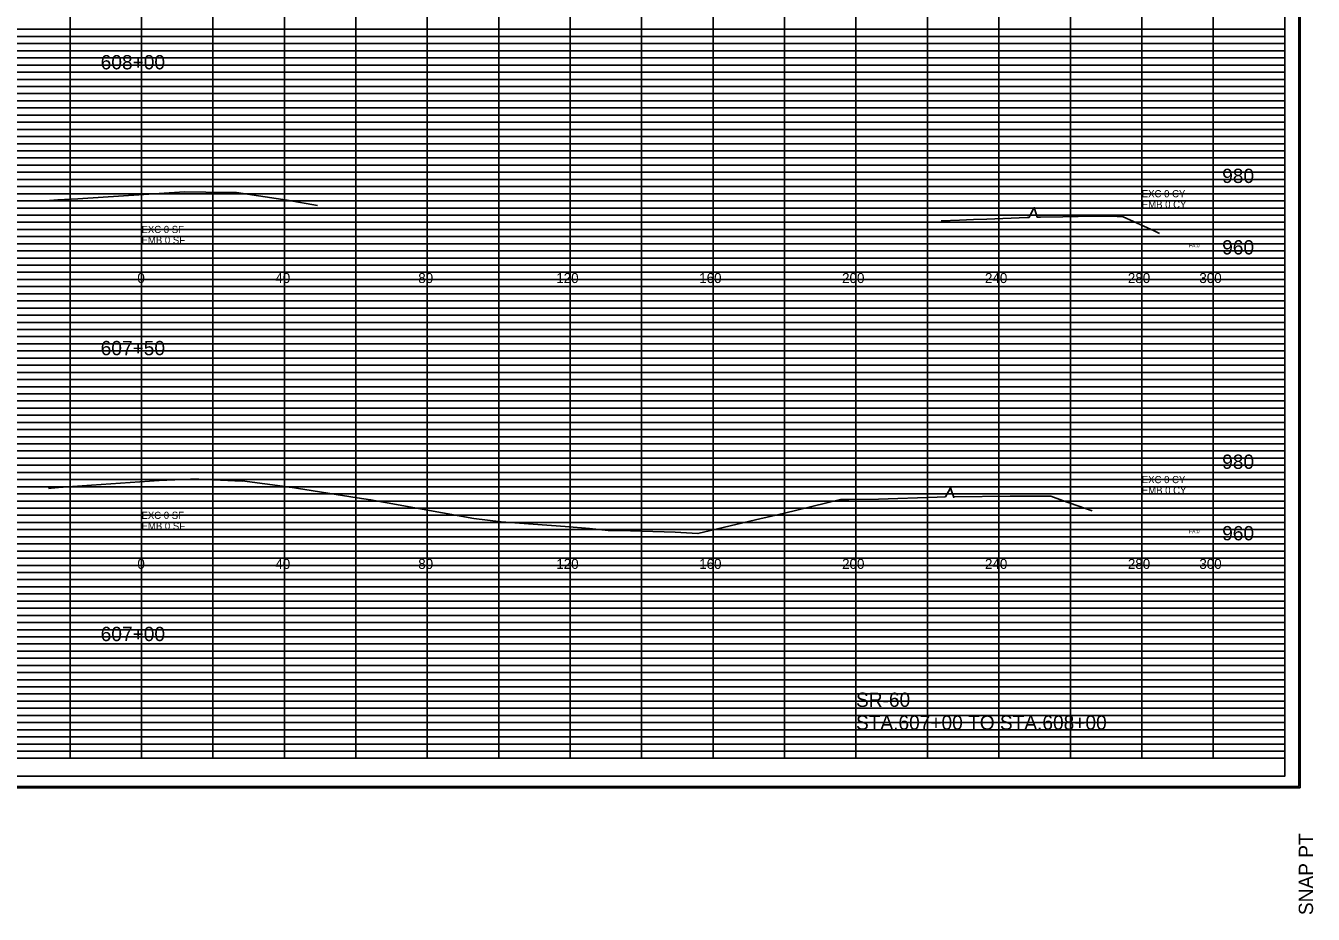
# Model space of a CAD drawing. Extents: x 2313580 to 2322968, y 282099 to 303247.
# Drawn here: x 2321124.9 to 2321485.3, y 287544 to 287792.7 of the extents above; entities that cross this region are included whole.
import ezdxf

# ---------------------------------------------------------------- set-up
doc = ezdxf.new("R2010")
doc.units = 0
for name, color, linetype in [('DESIGN - EARTHWORK - Excavation Limit Lines', 7, 'Continuous'), ('DESIGN - SHEET - Corner Text', 7, 'Continuous'), ('DESIGN - SHEET - Light Grid', 7, 'Continuous'), ('DESIGN - SHEET - Linework', 7, 'Continuous'), ('DESIGN - SHEET - Plot Shape', 7, 'Continuous'), ('DESIGN - TYPICAL - Text', 7, 'Continuous'), ('Prop_ CL text', 7, 'Continuous'), ('SURVEY - GROUND - Top of Ground', 7, 'Continuous')]:
    doc.layers.add(name, color=color, linetype=linetype)

msp = doc.modelspace()

# ---------------------------------------------------------------- linework, layer by layer
at = {"layer": 'DESIGN - SHEET - Light Grid'}
for p, q in [((2320997.28, 287791.67), (2321157.28, 287791.67)), ((2320997.28, 287789.67), (2321157.28, 287789.67)), ((2321157.28, 287791.67), (2321317.28, 287791.67)), ((2321157.28, 287789.67), (2321317.28, 287789.67)), ((2321317.28, 287791.67), (2321477.28, 287791.67)), ((2321317.28, 287789.67), (2321477.28, 287789.67)), ((2320997.28, 287785.67), (2321157.28, 287785.67)), ((2320997.28, 287783.67), (2321157.28, 287783.67)), ((2321157.28, 287785.67), (2321317.28, 287785.67)), ((2321157.28, 287783.67), (2321317.28, 287783.67)), ((2321317.28, 287785.67), (2321477.28, 287785.67)), ((2321317.28, 287783.67), (2321477.28, 287783.67)), ((2320997.28, 287781.67), (2321157.28, 287781.67)), ((2320997.28, 287779.67), (2321157.28, 287779.67)), ((2321157.28, 287781.67), (2321317.28, 287781.67)), ((2321157.28, 287779.67), (2321317.28, 287779.67)), ((2321317.28, 287781.67), (2321477.28, 287781.67)), ((2321317.28, 287779.67), (2321477.28, 287779.67)), ((2320997.28, 287777.67), (2321157.28, 287777.67)), ((2320997.28, 287775.67), (2321157.28, 287775.67)), ((2321157.28, 287777.67), (2321317.28, 287777.67)), ((2321157.28, 287775.67), (2321317.28, 287775.67)), ((2321317.28, 287777.67), (2321477.28, 287777.67)), ((2321317.28, 287775.67), (2321477.28, 287775.67)), ((2320997.28, 287773.67), (2321157.28, 287773.67)), ((2320997.28, 287771.67), (2321157.28, 287771.67)), ((2321157.28, 287773.67), (2321317.28, 287773.67)), ((2321157.28, 287771.67), (2321317.28, 287771.67)), ((2321317.28, 287773.67), (2321477.28, 287773.67)), ((2321317.28, 287771.67), (2321477.28, 287771.67)), ((2320997.28, 287769.67), (2321157.28, 287769.67)), ((2321157.28, 287769.67), (2321317.28, 287769.67)), ((2321317.28, 287769.67), (2321477.28, 287769.67)), ((2320997.28, 287765.67), (2321157.28, 287765.67)), ((2321157.28, 287765.67), (2321317.28, 287765.67)), ((2321317.28, 287765.67), (2321477.28, 287765.67)), ((2320997.28, 287763.67), (2321157.28, 287763.67)), ((2320997.28, 287761.67), (2321157.28, 287761.67)), ((2321157.28, 287763.67), (2321317.28, 287763.67)), ((2321157.28, 287761.67), (2321317.28, 287761.67)), ((2321317.28, 287763.67), (2321477.28, 287763.67)), ((2321317.28, 287761.67), (2321477.28, 287761.67)), ((2320997.28, 287759.67), (2321157.28, 287759.67)), ((2320997.28, 287757.67), (2321157.28, 287757.67)), ((2321157.28, 287759.67), (2321317.28, 287759.67)), ((2321157.28, 287757.67), (2321317.28, 287757.67)), ((2321317.28, 287759.67), (2321477.28, 287759.67)), ((2321317.28, 287757.67), (2321477.28, 287757.67)), ((2320997.28, 287755.67), (2321157.28, 287755.67)), ((2320997.28, 287753.67), (2321157.28, 287753.67)), ((2321157.28, 287755.67), (2321317.28, 287755.67)), ((2321157.28, 287753.67), (2321317.28, 287753.67)), ((2321317.28, 287755.67), (2321477.28, 287755.67)), ((2321317.28, 287753.67), (2321477.28, 287753.67)), ((2320997.28, 287751.67), (2321157.28, 287751.67)), ((2321157.28, 287751.67), (2321317.28, 287751.67)), ((2321317.28, 287751.67), (2321477.28, 287751.67)), ((2320997.28, 287749.67), (2321157.28, 287749.67)), ((2321157.28, 287749.67), (2321317.28, 287749.67)), ((2321317.28, 287749.67), (2321477.28, 287749.67)), ((2320997.28, 287745.67), (2321157.28, 287745.67)), ((2320997.28, 287743.67), (2321157.28, 287743.67)), ((2321157.28, 287745.67), (2321317.28, 287745.67)), ((2321157.28, 287743.67), (2321317.28, 287743.67)), ((2321317.28, 287745.67), (2321477.28, 287745.67)), ((2321317.28, 287743.67), (2321477.28, 287743.67)), ((2320997.28, 287741.67), (2321157.28, 287741.67)), ((2320997.28, 287739.67), (2321157.28, 287739.67)), ((2321157.28, 287741.67), (2321317.28, 287741.67)), ((2321157.28, 287739.67), (2321317.28, 287739.67)), ((2321317.28, 287741.67), (2321477.28, 287741.67)), ((2321317.28, 287739.67), (2321477.28, 287739.67)), ((2320997.28, 287737.67), (2321157.28, 287737.67)), ((2320997.28, 287735.67), (2321157.28, 287735.67)), ((2321157.28, 287737.67), (2321317.28, 287737.67)), ((2321157.28, 287735.67), (2321317.28, 287735.67)), ((2321317.28, 287737.67), (2321477.28, 287737.67)), ((2321317.28, 287735.67), (2321477.28, 287735.67)), ((2320997.28, 287733.67), (2321157.28, 287733.67)), ((2321157.28, 287733.67), (2321317.28, 287733.67)), ((2321317.28, 287733.67), (2321477.28, 287733.67)), ((2320997.28, 287731.67), (2321157.28, 287731.67)), ((2320997.28, 287729.67), (2321157.28, 287729.67)), ((2321157.28, 287731.67), (2321317.28, 287731.67)), ((2321157.28, 287729.67), (2321317.28, 287729.67)), ((2321317.28, 287731.67), (2321477.28, 287731.67)), ((2321317.28, 287729.67), (2321477.28, 287729.67)), ((2320997.28, 287725.67), (2321157.28, 287725.67)), ((2321157.28, 287725.67), (2321317.28, 287725.67)), ((2321317.28, 287725.67), (2321477.28, 287725.67)), ((2320997.28, 287723.67), (2321157.28, 287723.67)), ((2320997.28, 287721.67), (2321157.28, 287721.67)), ((2321157.28, 287723.67), (2321317.28, 287723.67)), ((2321157.28, 287721.67), (2321317.28, 287721.67)), ((2321317.28, 287723.67), (2321477.28, 287723.67)), ((2321317.28, 287721.67), (2321477.28, 287721.67)), ((2320997.28, 287719.67), (2321157.28, 287719.67)), ((2320997.28, 287717.67), (2321157.28, 287717.67)), ((2321157.28, 287719.67), (2321317.28, 287719.67)), ((2321157.28, 287717.67), (2321317.28, 287717.67)), ((2321317.28, 287719.67), (2321477.28, 287719.67)), ((2321317.28, 287717.67), (2321477.28, 287717.67)), ((2320997.28, 287715.67), (2321157.28, 287715.67)), ((2321157.28, 287715.67), (2321317.28, 287715.67)), ((2321317.28, 287715.67), (2321477.28, 287715.67)), ((2320997.28, 287713.67), (2321157.28, 287713.67)), ((2320997.28, 287711.67), (2321157.28, 287711.67)), ((2321157.28, 287713.67), (2321317.28, 287713.67)), ((2321157.28, 287711.67), (2321317.28, 287711.67)), ((2321317.28, 287713.67), (2321477.28, 287713.67)), ((2321317.28, 287711.67), (2321477.28, 287711.67)), ((2320997.28, 287709.67), (2321157.28, 287709.67)), ((2321157.28, 287709.67), (2321317.28, 287709.67)), ((2321317.28, 287709.67), (2321477.28, 287709.67)), ((2320997.28, 287705.67), (2321157.28, 287705.67)), ((2320997.28, 287703.67), (2321157.28, 287703.67)), ((2321157.28, 287705.67), (2321317.28, 287705.67)), ((2321157.28, 287703.67), (2321317.28, 287703.67)), ((2321317.28, 287705.67), (2321477.28, 287705.67)), ((2321317.28, 287703.67), (2321477.28, 287703.67)), ((2320997.28, 287701.67), (2321157.28, 287701.67)), ((2320997.28, 287699.67), (2321157.28, 287699.67)), ((2321157.28, 287701.67), (2321317.28, 287701.67)), ((2321157.28, 287699.67), (2321317.28, 287699.67)), ((2321317.28, 287701.67), (2321477.28, 287701.67)), ((2321317.28, 287699.67), (2321477.28, 287699.67)), ((2320997.28, 287697.67), (2321157.28, 287697.67)), ((2321157.28, 287697.67), (2321317.28, 287697.67)), ((2321317.28, 287697.67), (2321477.28, 287697.67)), ((2320997.28, 287695.67), (2321157.28, 287695.67)), ((2320997.28, 287693.67), (2321157.28, 287693.67)), ((2321157.28, 287695.67), (2321317.28, 287695.67)), ((2321157.28, 287693.67), (2321317.28, 287693.67)), ((2321317.28, 287695.67), (2321477.28, 287695.67)), ((2321317.28, 287693.67), (2321477.28, 287693.67)), ((2320997.28, 287691.67), (2321157.28, 287691.67)), ((2320997.28, 287689.67), (2321157.28, 287689.67)), ((2321157.28, 287691.67), (2321317.28, 287691.67)), ((2321157.28, 287689.67), (2321317.28, 287689.67)), ((2321317.28, 287691.67), (2321477.28, 287691.67)), ((2321317.28, 287689.67), (2321477.28, 287689.67)), ((2320997.28, 287685.67), (2321157.28, 287685.67)), ((2321157.28, 287685.67), (2321317.28, 287685.67)), ((2321317.28, 287685.67), (2321477.28, 287685.67)), ((2320997.28, 287683.67), (2321157.28, 287683.67)), ((2320997.28, 287681.67), (2321157.28, 287681.67)), ((2321157.28, 287683.67), (2321317.28, 287683.67)), ((2321157.28, 287681.67), (2321317.28, 287681.67)), ((2321317.28, 287683.67), (2321477.28, 287683.67)), ((2321317.28, 287681.67), (2321477.28, 287681.67)), ((2320997.28, 287679.67), (2321157.28, 287679.67)), ((2321157.28, 287679.67), (2321317.28, 287679.67)), ((2321317.28, 287679.67), (2321477.28, 287679.67)), ((2320997.28, 287677.67), (2321157.28, 287677.67)), ((2320997.28, 287675.67), (2321157.28, 287675.67)), ((2321157.28, 287677.67), (2321317.28, 287677.67)), ((2321157.28, 287675.67), (2321317.28, 287675.67)), ((2321317.28, 287677.67), (2321477.28, 287677.67)), ((2321317.28, 287675.67), (2321477.28, 287675.67)), ((2320997.28, 287673.67), (2321157.28, 287673.67)), ((2320997.28, 287671.67), (2321157.28, 287671.67)), ((2321157.28, 287673.67), (2321317.28, 287673.67)), ((2321157.28, 287671.67), (2321317.28, 287671.67)), ((2321317.28, 287673.67), (2321477.28, 287673.67)), ((2321317.28, 287671.67), (2321477.28, 287671.67)), ((2320997.28, 287669.67), (2321157.28, 287669.67)), ((2321157.28, 287669.67), (2321317.28, 287669.67)), ((2321317.28, 287669.67), (2321477.28, 287669.67)), ((2320997.28, 287665.67), (2321157.28, 287665.67)), ((2320997.28, 287663.67), (2321157.28, 287663.67)), ((2321157.28, 287665.67), (2321317.28, 287665.67)), ((2321157.28, 287663.67), (2321317.28, 287663.67)), ((2321317.28, 287665.67), (2321477.28, 287665.67)), ((2321317.28, 287663.67), (2321477.28, 287663.67)), ((2320997.28, 287661.67), (2321157.28, 287661.67)), ((2321157.28, 287661.67), (2321317.28, 287661.67)), ((2321317.28, 287661.67), (2321477.28, 287661.67)), ((2320997.28, 287659.67), (2321157.28, 287659.67)), ((2320997.28, 287657.67), (2321157.28, 287657.67)), ((2321157.28, 287659.67), (2321317.28, 287659.67)), ((2321157.28, 287657.67), (2321317.28, 287657.67)), ((2321317.28, 287659.67), (2321477.28, 287659.67)), ((2321317.28, 287657.67), (2321477.28, 287657.67)), ((2320997.28, 287655.67), (2321157.28, 287655.67)), ((2320997.28, 287653.67), (2321157.28, 287653.67)), ((2321157.28, 287655.67), (2321317.28, 287655.67)), ((2321157.28, 287653.67), (2321317.28, 287653.67)), ((2321317.28, 287655.67), (2321477.28, 287655.67)), ((2321317.28, 287653.67), (2321477.28, 287653.67)), ((2320997.28, 287651.67), (2321157.28, 287651.67)), ((2320997.28, 287649.67), (2321157.28, 287649.67)), ((2321157.28, 287651.67), (2321317.28, 287651.67)), ((2321157.28, 287649.67), (2321317.28, 287649.67)), ((2321317.28, 287651.67), (2321477.28, 287651.67)), ((2321317.28, 287649.67), (2321477.28, 287649.67)), ((2320997.28, 287645.67), (2321157.28, 287645.67)), ((2321157.28, 287645.67), (2321317.28, 287645.67)), ((2321317.28, 287645.67), (2321477.28, 287645.67)), ((2320997.28, 287643.67), (2321157.28, 287643.67)), ((2321157.28, 287643.67), (2321317.28, 287643.67)), ((2321317.28, 287643.67), (2321477.28, 287643.67)), ((2320997.28, 287641.67), (2321157.28, 287641.67)), ((2320997.28, 287639.67), (2321157.28, 287639.67)), ((2321157.28, 287641.67), (2321317.28, 287641.67)), ((2321157.28, 287639.67), (2321317.28, 287639.67)), ((2321317.28, 287641.67), (2321477.28, 287641.67)), ((2321317.28, 287639.67), (2321477.28, 287639.67)), ((2320997.28, 287637.67), (2321157.28, 287637.67)), ((2320997.28, 287635.67), (2321157.28, 287635.67)), ((2321157.28, 287637.67), (2321317.28, 287637.67)), ((2321157.28, 287635.67), (2321317.28, 287635.67)), ((2321317.28, 287637.67), (2321477.28, 287637.67)), ((2321317.28, 287635.67), (2321477.28, 287635.67)), ((2320997.28, 287633.67), (2321157.28, 287633.67)), ((2320997.28, 287631.67), (2321157.28, 287631.67)), ((2321157.28, 287633.67), (2321317.28, 287633.67)), ((2321157.28, 287631.67), (2321317.28, 287631.67)), ((2321317.28, 287633.67), (2321477.28, 287633.67)), ((2321317.28, 287631.67), (2321477.28, 287631.67)), ((2320997.28, 287629.67), (2321157.28, 287629.67)), ((2321157.28, 287629.67), (2321317.28, 287629.67)), ((2321317.28, 287629.67), (2321477.28, 287629.67)), ((2320997.28, 287625.67), (2321157.28, 287625.67)), ((2321157.28, 287625.67), (2321317.28, 287625.67)), ((2321317.28, 287625.67), (2321477.28, 287625.67)), ((2320997.28, 287623.67), (2321157.28, 287623.67)), ((2320997.28, 287621.67), (2321157.28, 287621.67)), ((2321157.28, 287623.67), (2321317.28, 287623.67)), ((2321157.28, 287621.67), (2321317.28, 287621.67)), ((2321317.28, 287623.67), (2321477.28, 287623.67)), ((2321317.28, 287621.67), (2321477.28, 287621.67)), ((2320997.28, 287619.67), (2321157.28, 287619.67)), ((2320997.28, 287617.67), (2321157.28, 287617.67)), ((2321157.28, 287619.67), (2321317.28, 287619.67)), ((2321157.28, 287617.67), (2321317.28, 287617.67)), ((2321317.28, 287619.67), (2321477.28, 287619.67)), ((2321317.28, 287617.67), (2321477.28, 287617.67)), ((2320997.28, 287615.67), (2321157.28, 287615.67)), ((2320997.28, 287613.67), (2321157.28, 287613.67)), ((2321157.28, 287615.67), (2321317.28, 287615.67)), ((2321157.28, 287613.67), (2321317.28, 287613.67)), ((2321317.28, 287615.67), (2321477.28, 287615.67)), ((2321317.28, 287613.67), (2321477.28, 287613.67)), ((2320997.28, 287611.67), (2321157.28, 287611.67)), ((2320997.28, 287609.67), (2321157.28, 287609.67)), ((2321157.28, 287611.67), (2321317.28, 287611.67)), ((2321157.28, 287609.67), (2321317.28, 287609.67)), ((2321317.28, 287611.67), (2321477.28, 287611.67)), ((2321317.28, 287609.67), (2321477.28, 287609.67)), ((2320997.28, 287605.67), (2321157.28, 287605.67)), ((2320997.28, 287603.67), (2321157.28, 287603.67)), ((2321157.28, 287605.67), (2321317.28, 287605.67)), ((2321157.28, 287603.67), (2321317.28, 287603.67)), ((2321317.28, 287605.67), (2321477.28, 287605.67)), ((2321317.28, 287603.67), (2321477.28, 287603.67)), ((2320997.28, 287601.67), (2321157.28, 287601.67)), ((2320997.28, 287599.67), (2321157.28, 287599.67)), ((2321157.28, 287601.67), (2321317.28, 287601.67)), ((2321157.28, 287599.67), (2321317.28, 287599.67)), ((2321317.28, 287601.67), (2321477.28, 287601.67)), ((2321317.28, 287599.67), (2321477.28, 287599.67)), ((2320997.28, 287597.67), (2321157.28, 287597.67)), ((2320997.28, 287595.67), (2321157.28, 287595.67)), ((2321157.28, 287597.67), (2321317.28, 287597.67)), ((2321157.28, 287595.67), (2321317.28, 287595.67)), ((2321317.28, 287597.67), (2321477.28, 287597.67)), ((2321317.28, 287595.67), (2321477.28, 287595.67)), ((2320997.28, 287593.67), (2321157.28, 287593.67)), ((2320997.28, 287591.67), (2321157.28, 287591.67)), ((2321157.28, 287593.67), (2321317.28, 287593.67)), ((2321157.28, 287591.67), (2321317.28, 287591.67)), ((2321317.28, 287593.67), (2321477.28, 287593.67)), ((2321317.28, 287591.67), (2321477.28, 287591.67)), ((2320997.28, 287589.67), (2321157.28, 287589.67)), ((2321157.28, 287589.67), (2321317.28, 287589.67)), ((2321317.28, 287589.67), (2321477.28, 287589.67))]:
    msp.add_line(p, q, dxfattribs=at)
at = {"layer": 'DESIGN - SHEET - Linework'}
for p, q in [((2321481.62, 288015.95), (2321481.62, 287579.39)), ((2321137.28, 287587.67), (2321137.28, 288007.67)), ((2321157.28, 287587.67), (2321157.28, 288007.67)), ((2321177.28, 287587.67), (2321177.28, 288007.67)), ((2321197.28, 287587.67), (2321197.28, 288007.67)), ((2321217.28, 287587.67), (2321217.28, 288007.67)), ((2321237.28, 287587.67), (2321237.28, 288007.67)), ((2321257.28, 287587.67), (2321257.28, 288007.67)), ((2321277.28, 287587.67), (2321277.28, 288007.67)), ((2321297.28, 287587.67), (2321297.28, 288007.67)), ((2321317.28, 287587.67), (2321317.28, 288007.67)), ((2321337.28, 287587.67), (2321337.28, 288007.67)), ((2321357.28, 287587.67), (2321357.28, 288007.67)), ((2321377.28, 287587.67), (2321377.28, 288007.67)), ((2321397.28, 287587.67), (2321397.28, 287987.67)), ((2321417.28, 287587.67), (2321417.28, 287987.67)), ((2321437.28, 287587.67), (2321437.28, 287987.67)), ((2321457.28, 287587.67), (2321457.28, 287987.67)), ((2320837.28, 287787.67), (2321477.28, 287787.67)), ((2320837.28, 287767.67), (2321477.28, 287767.67)), ((2320837.28, 287747.67), (2321477.28, 287747.67)), ((2320837.28, 287727.67), (2321477.28, 287727.67)), ((2320837.28, 287707.67), (2321477.28, 287707.67)), ((2320837.28, 287687.67), (2321477.28, 287687.67)), ((2320837.28, 287667.67), (2321477.28, 287667.67)), ((2320837.28, 287647.67), (2321477.28, 287647.67)), ((2320837.28, 287627.67), (2321477.28, 287627.67)), ((2320837.28, 287607.67), (2321477.28, 287607.67)), ((2320800.82, 287579.39), (2321481.62, 287579.39))]:
    msp.add_line(p, q, dxfattribs=at)
msp.add_lwpolyline([(2320837.28, 288007.67), (2320837.28, 287587.67), (2321477.28, 287587.67), (2321477.28, 288007.67), (2320837.28, 288007.67)], dxfattribs=at)
at = {"layer": 'DESIGN - SHEET - Plot Shape'}
for points in [[(2320801.22, 288015.55), (2321481.22, 288015.55), (2321481.22, 287579.79), (2320801.22, 287579.79)], [(2320820.28, 288007.67), (2321477.28, 288007.67), (2321477.28, 287582.67), (2320820.28, 287582.67)]]:
    msp.add_lwpolyline(points, close=True, dxfattribs=at)
at = {"layer": 'SURVEY - GROUND - Top of Ground'}
for points in [[(2321131.31, 287743.72), (2321131.34, 287743.72), (2321131.61, 287743.74), (2321133.87, 287743.91), (2321139.5, 287744.28), (2321169.28, 287746.24), (2321175.25, 287746.14), (2321183.91, 287746.01), (2321198.03, 287743.82), (2321206.55, 287742.39)], [(2321381.11, 287738.07), (2321386.28, 287738.29), (2321390.14, 287738.47), (2321393.94, 287738.59), (2321405.17, 287738.98), (2321405.75, 287739.03), (2321405.75, 287739.04), (2321406.44, 287740.43), (2321407.19, 287741.81), (2321407.63, 287740.36), (2321408.03, 287739.1), (2321408.94, 287739.1), (2321415.22, 287739.19), (2321423.87, 287739.38), (2321430.4, 287739.27), (2321432.04, 287739.24), (2321440.7, 287735.29), (2321442.26, 287734.53)], [(2321131.28, 287663.22), (2321131.4, 287663.23), (2321131.99, 287663.28), (2321134.04, 287663.47), (2321143.33, 287664.14), (2321162.26, 287665.4), (2321170.99, 287665.82), (2321173.37, 287665.78), (2321185.48, 287665.25), (2321185.48, 287665.35), (2321198.14, 287663.61), (2321198.59, 287663.55), (2321198.88, 287663.51), (2321217.67, 287660.57), (2321221.4, 287660.03), (2321224.99, 287659.39), (2321250.28, 287654.8), (2321257.98, 287653.85), (2321275.88, 287652.54), (2321282.71, 287651.98), (2321287.87, 287651.42), (2321289.01, 287651.39), (2321291.08, 287651.38), (2321306.65, 287650.99), (2321313.01, 287650.57), (2321329.17, 287654.43), (2321336.92, 287656.15), (2321352.94, 287660.08), (2321355.3, 287660.09), (2321363.59, 287660.17), (2321369.01, 287660.34), (2321379.97, 287660.74), (2321382.19, 287660.81), (2321382.27, 287660.82), (2321382.31, 287660.81), (2321383.51, 287662.95), (2321383.77, 287663.62), (2321383.77, 287663.62), (2321383.91, 287662.81), (2321384.65, 287660.66), (2321384.85, 287660.85), (2321400.48, 287661.01), (2321403.14, 287661.03), (2321408.21, 287661.03), (2321411.78, 287661.05), (2321415.13, 287659.82), (2321423.38, 287656.92)]]:
    msp.add_lwpolyline(points, dxfattribs=at)

# ---------------------------------------------------------------- texts
at = {"layer": 'DESIGN - EARTHWORK - Excavation Limit Lines'}
for s, p in [('EXC 0 CY', (2321437.28, 287744.67)), ('EMB 0 CY', (2321437.28, 287741.67)), ('EXC 0 SF', (2321157.28, 287734.67)), ('EMB 0 SF', (2321157.28, 287731.67)), ('EXC 0 CY', (2321437.28, 287664.67)), ('EMB 0 CY', (2321437.28, 287661.67)), ('EXC 0 SF', (2321157.28, 287654.67)), ('EMB 0 SF', (2321157.28, 287651.67))]:
    msp.add_text(s, height=2, dxfattribs=at).set_placement(p)
at = {"layer": 'DESIGN - SHEET - Corner Text'}
msp.add_text('SNAP PT  ', height=4, rotation=90, dxfattribs=at).set_placement((2321485.22, 287543.79))
at = {"layer": 'DESIGN - TYPICAL - Text'}
for s, height, p in [('608+00', 4, (2321145.86, 287780.47)), ('980', 4, (2321459.78, 287748.67)), ('960', 4, (2321459.78, 287728.67)), ('0', 2.8, (2321156.12, 287720.67)), ('40', 2.8, (2321194.75, 287720.67)), ('80', 2.8, (2321234.75, 287720.67)), ('120', 2.8, (2321273.39, 287720.67)), ('160', 2.8, (2321313.39, 287720.67)), ('200', 2.8, (2321353.39, 287720.67)), ('240', 2.8, (2321393.39, 287720.67)), ('280', 2.8, (2321433.39, 287720.67)), ('300', 2.8, (2321453.39, 287720.67)), ('607+50', 4, (2321145.86, 287700.47)), ('980', 4, (2321459.78, 287668.67)), ('960', 4, (2321459.78, 287648.67)), ('0', 2.8, (2321156.12, 287640.67)), ('40', 2.8, (2321194.75, 287640.67)), ('80', 2.8, (2321234.75, 287640.67)), ('120', 2.8, (2321273.39, 287640.67)), ('160', 2.8, (2321313.39, 287640.67)), ('200', 2.8, (2321353.39, 287640.67)), ('240', 2.8, (2321393.39, 287640.67)), ('280', 2.8, (2321433.39, 287640.67)), ('300', 2.8, (2321453.39, 287640.67)), ('607+00', 4, (2321145.86, 287620.47)), ('SR-60', 4, (2321357.28, 287602.05)), ('STA.607+00 TO STA.608+00', 4, (2321357.28, 287595.67))]:
    msp.add_text(s, height=height, dxfattribs=at).set_placement(p)
at = {"layer": 'Prop_ CL text'}
for p in [(2321450.52, 287730.67), (2321450.52, 287650.67)]:
    msp.add_text('FA:0', height=1, dxfattribs=at).set_placement(p)

doc.saveas('drawing.dxf')
